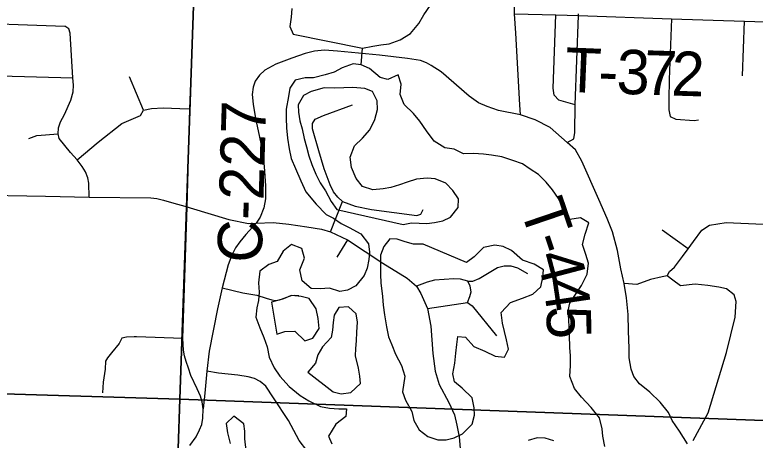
# Model space of a CAD drawing. Extents: x 0 to 34, y 0 to 22.
# Drawn here: x 7.099 to 8.046, y 17.828 to 18.372 of the extents above; entities that cross this region are included whole.
import ezdxf

# ---------------------------------------------------------------- set-up
doc = ezdxf.new("R2010")
doc.units = 0
for name, color, linetype in [('GM_X_Corporation', 7, 'Continuous'), ('GM_X_County_Road', 7, 'Continuous'), ('GM_X_County_Road_Text', 7, 'Continuous'), ('GM_X_Major_Lake', 7, 'Continuous'), ('GM_X_Minor_Lake', 7, 'Continuous'), ('GM_X_Minor_River', 7, 'Continuous'), ('GM_X_Township_Road', 7, 'Continuous'), ('GM_X_Township_Road_Text', 7, 'Continuous')]:
    doc.layers.add(name, color=color, linetype=linetype)

msp = doc.modelspace()

# ---------------------------------------------------------------- linework, layer by layer
at = {"layer": 'GM_X_Corporation'}
for points in [[(6.3228, 18.92136), (7.34478, 18.88792), (7.30996, 17.88061), (6.2808, 17.91168)], [(7.34478, 18.88792), (8.33332, 18.86242), (8.30127, 17.84453), (7.30996, 17.88061)], [(7.30996, 17.88061), (7.27561, 16.87038), (6.24525, 16.90712), (6.2808, 17.91168)], [(8.30127, 17.84453), (8.26687, 16.83772), (7.27561, 16.87038), (7.30996, 17.88061)]]:
    msp.add_lwpolyline(points, close=True, dxfattribs=at)
at = {"layer": 'GM_X_County_Road'}
for points in [[(7.332, 17.89366), (7.32398, 17.9111), (7.32078, 17.92041), (7.31812, 17.92893), (7.31578, 17.9359), (7.31457, 17.9433), (7.31386, 17.9582), (7.31908, 18.12659), (7.32243, 18.25211), (7.32587, 18.34106), (7.33158, 18.51382), (7.33284, 18.5568), (7.3335, 18.59032), (7.33423, 18.62555), (7.33538, 18.66314), (7.3371, 18.71902), (7.33882, 18.774), (7.33937, 18.8288), (7.34061, 18.89137)], [(7.32256, 17.82132), (7.33054, 17.83232), (7.3348, 17.84119), (7.33799, 17.84829), (7.33941, 17.85609), (7.33986, 17.86821), (7.33844, 17.8773), (7.33622, 17.88448), (7.332, 17.89366)]]:
    msp.add_lwpolyline(points, dxfattribs=at)
at = {"layer": 'GM_X_Major_Lake'}
for points in [[(7.53131, 18.30982), (7.51734, 18.30468), (7.50718, 18.29922), (7.49584, 18.29564), (7.48072, 18.29201), (7.4701, 18.29186), (7.45724, 18.28864), (7.45055, 18.27867), (7.4488, 18.26801), (7.44598, 18.25163), (7.44576, 18.24023), (7.44631, 18.2277), (7.44763, 18.21442), (7.44971, 18.20077), (7.45215, 18.18864), (7.45764, 18.1758), (7.46468, 18.15994), (7.47094, 18.14597), (7.48405, 18.1302), (7.49675, 18.11708), (7.5063, 18.11227), (7.51625, 18.10557), (7.52618, 18.10039), (7.54109, 18.09224), (7.55113, 18.07947), (7.55241, 18.06885), (7.5514, 18.05933), (7.54927, 18.04829), (7.54561, 18.03873), (7.53479, 18.02566), (7.52424, 18.0202), (7.5144, 18.01854), (7.50107, 18.02253), (7.48932, 18.02161), (7.47755, 18.0222), (7.46604, 18.03192), (7.46318, 18.04632), (7.46905, 18.06122), (7.46586, 18.07333), (7.45251, 18.07846), (7.442, 18.06996), (7.43421, 18.05693), (7.42364, 18.05298), (7.412, 18.04446), (7.4103, 18.02962), (7.41122, 18.01747), (7.41023, 18.00682), (7.40846, 17.9973), (7.40711, 17.9855), (7.41222, 17.97189), (7.41732, 17.95942), (7.42128, 17.9477), (7.42411, 17.93444), (7.43037, 17.92085), (7.43772, 17.90994), (7.44966, 17.89681), (7.46347, 17.88522), (7.47457, 17.87854), (7.48984, 17.87116), (7.50125, 17.86903), (7.51302, 17.86844), (7.52289, 17.8682), (7.52226, 17.85831), (7.50911, 17.84863), (7.49984, 17.8333), (7.50414, 17.82348)], [(7.8532, 17.82002), (7.85075, 17.83329), (7.84986, 17.84277), (7.84626, 17.85678), (7.83583, 17.86993), (7.82352, 17.88306), (7.81464, 17.89433), (7.80836, 17.90982), (7.80931, 17.92351), (7.80952, 17.93606), (7.80862, 17.94668), (7.80802, 17.96263), (7.80751, 17.97212), (7.807, 17.98237), (7.80646, 17.99377), (7.80861, 18.00329), (7.81492, 18.01326), (7.82347, 18.02592), (7.83049, 18.04046), (7.83219, 18.05454), (7.829, 18.06589), (7.82466, 18.07875), (7.82828, 18.09172), (7.83263, 18.10622), (7.8223, 18.11253), (7.80867, 18.11044), (7.80013, 18.12476), (7.79389, 18.13721), (7.78615, 18.1485), (7.77843, 18.15827), (7.76844, 18.16801), (7.75772, 18.17508), (7.74814, 18.18178), (7.73557, 18.18616), (7.72147, 18.19052), (7.70816, 18.193), (7.6979, 18.19399), (7.68537, 18.19496), (7.67248, 18.1944), (7.66063, 18.20069), (7.64886, 18.20204), (7.63508, 18.21097), (7.62504, 18.22413), (7.61652, 18.23654), (7.60842, 18.24631), (7.59651, 18.25754), (7.5914, 18.27039), (7.59274, 18.2837), (7.58916, 18.29581), (7.57559, 18.28954), (7.56607, 18.29245), (7.55226, 18.30365), (7.54157, 18.30844), (7.53131, 18.30982)], [(7.59556, 18.10403), (7.60615, 18.10646), (7.61602, 18.10584), (7.62551, 18.10559), (7.63536, 18.10649), (7.64595, 18.10891), (7.65575, 18.11361), (7.66582, 18.12591), (7.66605, 18.13693), (7.65908, 18.14747), (7.64984, 18.15722), (7.63611, 18.16273), (7.62624, 18.16335), (7.61222, 18.16201), (7.60051, 18.15843), (7.59069, 18.15487), (7.57974, 18.1513), (7.5699, 18.14964), (7.55664, 18.14832), (7.54331, 18.15269), (7.5352, 18.16321), (7.52932, 18.17719), (7.52762, 18.19046), (7.53311, 18.20498), (7.54322, 18.21462), (7.55256, 18.22539), (7.55921, 18.2384), (7.56245, 18.25136), (7.5623, 18.26238), (7.55607, 18.27445), (7.54653, 18.27812), (7.53096, 18.27942), (7.51959, 18.27888), (7.50707, 18.2787), (7.49417, 18.2789), (7.47754, 18.27449), (7.46775, 18.26903), (7.46108, 18.25716), (7.46159, 18.24767), (7.46326, 18.23667), (7.46605, 18.22645), (7.46887, 18.21433), (7.47168, 18.20336), (7.47487, 18.192), (7.47881, 18.18104), (7.48391, 18.16857), (7.48937, 18.15725), (7.49596, 18.14709), (7.50335, 18.13351), (7.5107, 18.12335)], [(7.5107, 18.12335), (7.59556, 18.10403)], [(7.62093, 18.07893), (7.60879, 18.07914), (7.59775, 18.08202), (7.58785, 18.0853), (7.57835, 18.08593), (7.57052, 18.07594), (7.5665, 18.06487), (7.56625, 18.05498), (7.56646, 18.04017), (7.56698, 18.02954), (7.56911, 18.01209), (7.57002, 18.00108), (7.57171, 17.98857), (7.57419, 17.97302), (7.57664, 17.96052), (7.58096, 17.94994), (7.58567, 17.93823), (7.59307, 17.9239), (7.59743, 17.9099), (7.59467, 17.8901), (7.59823, 17.87913), (7.60639, 17.86481), (7.6092, 17.85345), (7.61581, 17.84139), (7.62693, 17.83281), (7.63989, 17.82843), (7.65051, 17.82858), (7.66072, 17.831), (7.67127, 17.83609), (7.68362, 17.8488), (7.6865, 17.86024), (7.68637, 17.86973), (7.68354, 17.88223), (7.67086, 17.89459), (7.66088, 17.90281), (7.65885, 17.91304), (7.66132, 17.92676), (7.66266, 17.93969), (7.66403, 17.95073), (7.66541, 17.96063), (7.6749, 17.96), (7.68569, 17.94799), (7.6998, 17.94211), (7.71317, 17.93546), (7.72494, 17.93449), (7.73012, 17.94444), (7.72768, 17.95656), (7.72488, 17.96716), (7.72246, 17.97777), (7.72076, 17.99142), (7.73272, 18.00413), (7.74782, 18.00966), (7.76103, 18.01516), (7.77152, 18.02443), (7.77401, 18.03662), (7.77464, 18.04613), (7.76279, 18.05318), (7.74792, 18.05829), (7.73409, 18.07102), (7.72341, 18.07581), (7.71276, 18.07756), (7.698, 18.07469), (7.68603, 18.06274), (7.67626, 18.05539)], [(7.67626, 18.05539), (7.62093, 18.07893)], [(7.43396, 17.96384), (7.44415, 17.9674), (7.45705, 17.96758), (7.46973, 17.95522), (7.47993, 17.95878), (7.48811, 17.97106), (7.48679, 17.98396), (7.48435, 17.99608), (7.47507, 18.00925), (7.46479, 18.01214), (7.45301, 18.01312), (7.43942, 18.00837), (7.42695, 18.00477)], [(7.42695, 18.00477), (7.43396, 17.96384)], [(7.5059, 17.89), (7.51618, 17.88748), (7.52867, 17.88918), (7.54065, 17.90074), (7.54014, 17.91023), (7.53811, 17.92047), (7.53448, 17.93599), (7.53473, 17.94549), (7.53574, 17.95539), (7.53635, 17.96641), (7.53693, 17.97934), (7.53527, 17.98996), (7.52528, 17.99893), (7.51316, 17.99801), (7.50722, 17.98804), (7.50583, 17.97852), (7.50521, 17.96902), (7.50344, 17.95949), (7.49222, 17.94756), (7.48629, 17.93722), (7.4834, 17.92654), (7.47331, 17.91538)], [(7.47331, 17.91538), (7.5059, 17.89)], [(7.39463, 17.81473), (7.39291, 17.8299), (7.39277, 17.83977), (7.3915, 17.84926), (7.37886, 17.85896), (7.36912, 17.84932), (7.3708, 17.83757), (7.37402, 17.82393)], [(7.78823, 17.82747), (7.77681, 17.83073), (7.76656, 17.83134), (7.75522, 17.82777)]]:
    msp.add_lwpolyline(points, dxfattribs=at)
at = {"layer": 'GM_X_Minor_Lake'}
for points in [[(7.54318, 18.32974), (7.5568, 18.33221), (7.56664, 18.33387), (7.57763, 18.33516), (7.59159, 18.3403), (7.60476, 18.34847), (7.61558, 18.36154), (7.62189, 18.37226), (7.63044, 18.38492)], [(7.45296, 18.38053), (7.45235, 18.3695), (7.45061, 18.3577), (7.45455, 18.3475)], [(7.45455, 18.3475), (7.54318, 18.32974)]]:
    msp.add_lwpolyline(points, dxfattribs=at)
at = {"layer": 'GM_X_Minor_River'}
msp.add_lwpolyline([(7.54157, 18.30844), (7.54318, 18.32974)], dxfattribs=at)
at = {"layer": 'GM_X_Township_Road'}
for p, q in [((8.02941, 18.29448), (8.03185, 18.36434)), ((7.26319, 18.2503), (7.24553, 18.29327)), ((7.95996, 18.07313), (7.92662, 18.09696)), ((7.52419, 18.08431), (7.5107, 18.06248))]:
    msp.add_line(p, q, dxfattribs=at)
for points in [[(7.74556, 18.24437), (7.74465, 18.25726), (7.73926, 18.34897), (7.73776, 18.37355), (7.73806, 18.39872), (7.74463, 18.47662), (7.74385, 18.48653)], [(6.8449, 18.36733), (6.9935, 18.36338), (7.01961, 18.36295), (7.16272, 18.35811)], [(7.73776, 18.37355), (7.79057, 18.37241), (7.81938, 18.37153), (7.93855, 18.36717), (8.03185, 18.36434), (8.11129, 18.36165), (8.31578, 18.35708)], [(7.81545, 18.25717), (7.7945, 18.26328), (7.78839, 18.26983), (7.78708, 18.27856), (7.79057, 18.37241)], [(7.80498, 18.20915), (7.81371, 18.21395), (7.81502, 18.22181), (7.81545, 18.25717), (7.81938, 18.37153), (7.81944, 18.37353)], [(7.93855, 18.36717), (7.93566, 18.2898), (7.93528, 18.26417), (7.93528, 18.25097), (7.93683, 18.24244), (7.94382, 18.23895), (7.9675, 18.23739), (7.97293, 18.23817)], [(7.17992, 18.18536), (7.17872, 18.18707), (7.1702, 18.19612), (7.15555, 18.21423), (7.15404, 18.22035), (7.15484, 18.22799), (7.15724, 18.23545), (7.1625, 18.24508), (7.17063, 18.2633), (7.17326, 18.27405), (7.17392, 18.28261), (7.17304, 18.29183), (7.16975, 18.34911), (7.16804, 18.35431), (7.16272, 18.35811)], [(7.95907, 17.82345), (7.94872, 17.83981), (7.93936, 17.85336), (7.93452, 17.86336), (7.9242, 17.87692), (7.91097, 17.8895), (7.89774, 17.90015), (7.89032, 17.9095), (7.88709, 17.91918), (7.88451, 17.93338), (7.88419, 17.94532), (7.88354, 17.96823), (7.88322, 17.98888), (7.88096, 18.01018), (7.87797, 18.02862), (7.87386, 18.0476), (7.86935, 18.07084), (7.86322, 18.09471), (7.85605, 18.11181), (7.84557, 18.13626), (7.82375, 18.18515), (7.81589, 18.19955), (7.80498, 18.20915), (7.78332, 18.22818), (7.76413, 18.23808), (7.74556, 18.24437), (7.71738, 18.25006), (7.70269, 18.25516), (7.69161, 18.25995), (7.67962, 18.26835), (7.64395, 18.29952), (7.63137, 18.30761), (7.62537, 18.31091), (7.61735, 18.31412), (7.60089, 18.3167), (7.56508, 18.3209), (7.51151, 18.32574), (7.49474, 18.32703), (7.48183, 18.32574), (7.47021, 18.32316), (7.45311, 18.31703), (7.43246, 18.30928), (7.41859, 18.30154), (7.41181, 18.29541), (7.40633, 18.28734), (7.40375, 18.27992), (7.40246, 18.27056), (7.40342, 18.25798), (7.40665, 18.23991), (7.41011, 18.22385), (7.41503, 18.19979), (7.41762, 18.17831), (7.41917, 18.15347), (7.41943, 18.13691), (7.4171, 18.12527), (7.41244, 18.11337), (7.40759, 18.10581), (7.39433, 18.09137), (7.38657, 18.08179), (7.38095, 18.07416), (7.37632, 18.0651), (7.37151, 18.05232), (7.3641, 18.02327), (7.35799, 17.99607), (7.34739, 17.94205), (7.34437, 17.91643), (7.34163, 17.88821), (7.33986, 17.86821)], [(7.06966, 18.28964), (7.07954, 18.29446), (7.17304, 18.29183)], [(7.17872, 18.18707), (7.20552, 18.20944), (7.23553, 18.23358), (7.25961, 18.24378), (7.26319, 18.2503), (7.2737, 18.25266), (7.28837, 18.25338), (7.30975, 18.25247), (7.32243, 18.25211)], [(7.51793, 18.13337), (7.51182, 18.13893), (7.50612, 18.14602), (7.50195, 18.15492), (7.4943, 18.17535), (7.48735, 18.19828), (7.47957, 18.22644), (7.47957, 18.23317), (7.48304, 18.23885), (7.49344, 18.2438), (7.53072, 18.25722)], [(7.11676, 18.21405), (7.12688, 18.21814), (7.15404, 18.22035)], [(7.19381, 18.13913), (7.19346, 18.15689), (7.19203, 18.16364), (7.18937, 18.17145), (7.18476, 18.17855), (7.17992, 18.18536)], [(6.94077, 18.14529), (7.04167, 18.14201), (7.13786, 18.14019)], [(7.13786, 18.14019), (7.19381, 18.13913), (7.27263, 18.13825), (7.28035, 18.1373), (7.28876, 18.1351), (7.29937, 18.13225), (7.31908, 18.12659), (7.32289, 18.12545)], [(7.5025, 18.09473), (7.51793, 18.13337), (7.53406, 18.12767), (7.5549, 18.1235), (7.61302, 18.1155), (7.61787, 18.11753), (7.62107, 18.1235)], [(7.32289, 18.12545), (7.37247, 18.11064), (7.3976, 18.10544), (7.40759, 18.10581), (7.42911, 18.10655), (7.44899, 18.10446), (7.47234, 18.10113), (7.49083, 18.09835), (7.5025, 18.09473), (7.52419, 18.08431), (7.5695, 18.05484), (7.60036, 18.03566), (7.61231, 18.0251), (7.61787, 18.01564), (7.62635, 17.99646), (7.63079, 17.97395), (7.6333, 17.93906), (7.63649, 17.91654), (7.64136, 17.89958), (7.65387, 17.87651), (7.66123, 17.86067), (7.66401, 17.84732), (7.66679, 17.83245), (7.66985, 17.79715)], [(7.93281, 18.03863), (7.93603, 18.04383), (7.94229, 18.04969), (7.95262, 18.06299), (7.95996, 18.07313), (7.96656, 18.08224), (7.9773, 18.09668), (7.98699, 18.10316), (8.00831, 18.10658), (8.05591, 18.10451), (8.10151, 18.10022)], [(7.67791, 18.03149), (7.68445, 18.03177), (7.69251, 18.03496), (7.71614, 18.04914), (7.72462, 18.05137), (7.73309, 18.05123), (7.74157, 18.04886), (7.75422, 18.0415)], [(7.966, 17.82782), (7.98545, 17.8632), (8.00869, 17.94023), (8.01979, 17.98541), (8.02128, 18.00548), (8.01856, 18.01393), (8.00901, 18.02187), (7.99888, 18.02413), (7.98495, 18.02614), (7.96874, 18.02786), (7.95012, 18.02549), (7.94017, 18.03305), (7.93281, 18.03863), (7.92671, 18.03734), (7.91144, 18.0337), (7.89419, 18.02748), (7.87797, 18.02862)], [(7.62635, 17.99646), (7.67777, 18.00425), (7.68055, 18.01189), (7.68222, 18.01815), (7.68111, 18.0251), (7.67791, 18.03149), (7.6686, 18.03399), (7.66012, 18.03455), (7.63552, 18.03288), (7.62621, 18.03038), (7.61231, 18.0251)], [(7.3641, 18.02327), (7.39038, 18.01679), (7.40815, 18.01365), (7.42036, 18.00995), (7.42739, 18.00791), (7.4322, 18.00699), (7.43721, 18.00754), (7.44294, 18.00958), (7.45182, 18.01328), (7.45682, 18.01365), (7.462, 18.01328)], [(7.67777, 18.00425), (7.68347, 18.00008), (7.71475, 17.96185)], [(7.25141, 17.96032), (7.24146, 17.96011), (7.23553, 17.9585), (7.23224, 17.95182), (7.22231, 17.93975), (7.2172, 17.9337), (7.21478, 17.92912), (7.21432, 17.91917), (7.21184, 17.90249), (7.21077, 17.88883)], [(7.31386, 17.9582), (7.2544, 17.96038), (7.25141, 17.96032)], [(7.49661, 17.64462), (7.48656, 17.65276), (7.47543, 17.66472), (7.46913, 17.67165), (7.4655, 17.68006), (7.46314, 17.69642), (7.45706, 17.71588), (7.45238, 17.72924), (7.4621, 17.74501), (7.47373, 17.76227), (7.48204, 17.78375), (7.48039, 17.79782), (7.472, 17.81504), (7.4623, 17.82778), (7.44889, 17.85317), (7.42955, 17.88226), (7.41979, 17.89717), (7.41248, 17.90324), (7.40547, 17.90702), (7.39699, 17.9093), (7.38418, 17.91133), (7.35925, 17.91389), (7.34437, 17.91643)]]:
    msp.add_lwpolyline(points, dxfattribs=at)

# ---------------------------------------------------------------- texts
at = {"layer": 'GM_X_County_Road_Text'}
msp.add_text('C-227', height=0.056818, rotation=88.34754, dxfattribs=at).set_placement((7.4144, 18.05463))
at = {"layer": 'GM_X_Township_Road_Text'}
for s, rotation, p in [('T', 357.53074, (7.80117, 18.27411)), ('3', 358.16686, (7.86764, 18.27147)), ('7', 358.18929, (7.90264, 18.27035)), ('2', 358.20484, (7.93764, 18.26925)), ('-', 358.07478, (7.84422, 18.27226)), ('T', 288.84693, (7.74407, 18.12559)), ('-', 288.57318, (7.75778, 18.08543)), ('4', 284.77085, (7.76493, 18.06427)), ('4', 278.51868, (7.77352, 18.03203)), ('5', 271.34796, (7.77854, 17.99929))]:
    msp.add_text(s, height=0.05682, rotation=rotation, dxfattribs=at).set_placement(p)

doc.saveas('drawing.dxf')
